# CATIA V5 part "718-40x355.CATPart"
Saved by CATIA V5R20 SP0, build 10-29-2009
Part number: 718-40x355
Definition: NONE
Nomenclature: 718-40x355
Source: Unknown
Description: 718-40x355
Bounding box of the stored display mesh (mm): x 0 to 392, y -25 to 25, z -25 to 25
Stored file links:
  C:\Users\Utente\Desktop\IO LAVORO\3D X SITO CF\X SITO\718\718-40x355.CATPart
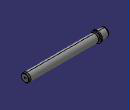
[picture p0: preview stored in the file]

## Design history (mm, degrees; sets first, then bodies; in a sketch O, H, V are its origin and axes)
Body1 "718-40x355" (main body)
  Solid1: solid without history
